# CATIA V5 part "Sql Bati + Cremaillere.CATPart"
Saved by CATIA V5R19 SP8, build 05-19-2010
Part number: Sql Bati + Cremaillere
Publications: "Plan.1", "Point.2", "Plan.3", "Droite.1", "Point.4", "Plan.4", "Point.6", "Point.8", "demi largeur base", "Plan.5", "Plan.7"
Bounding box of the stored display mesh (mm): x 0 to 0, y -950 to 470, z -1670 to 0
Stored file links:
  G:\EU_thinkMotion\CFAO_2010\MMS_groupe3\MMS_groupe3\rdalborgo\rdalborgo\Sql Bati + Cremaillere.CATPart
  G:\EU_thinkMotion\CFAO_2010\MMS_groupe3\MMS_groupe3\rdalborgo\rdalborgo\rdalborgo.CATProduct
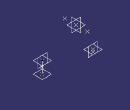
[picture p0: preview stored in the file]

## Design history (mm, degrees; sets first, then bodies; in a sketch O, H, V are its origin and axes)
Parameters
  `demi largeur base` = 320 mm {= 70mm+External.entraxe /2}
External parameters (linked from other documents)
  External.entraxe = 500 mm
Set1
  Plane1: linked copy from another document
  Point1 "Cremaillere": linked copy from another document
  Point2 "A verin frein": linked copy from another document
  Point3 "A verin para": linked copy from another document
  Point4 "Origine": linked copy from another document
  Plane2: linked copy from another document
  Plane3: linked copy from another document
Set2
  Plane4: type OffsetPt, RefPlane Plane1, RefPoint Point1
  Point5: (0, 0, 160), relative to Point2
  Plane5: type OffsetPt, RefPlane Plane1, RefPoint Point5
  Line1: type PtPt, FirstPoint Point1, SecondPoint Point5
  Point6: (0, 0, 65), relative to Point3
  Plane6: type OffsetPt, RefPlane Plane1, RefPoint Point6
  Point7: (0, 320 {= `demi largeur base`}, 0), relative to Point4
  Point8: (0, -320 {= -`demi largeur base`}, 0)
  Plane7: type OffsetPt, RefPlane Plane2, RefPoint Point6
  Plane8: type OffsetPt, RefPlane Plane2, RefPoint Point5
Body1 (main body)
